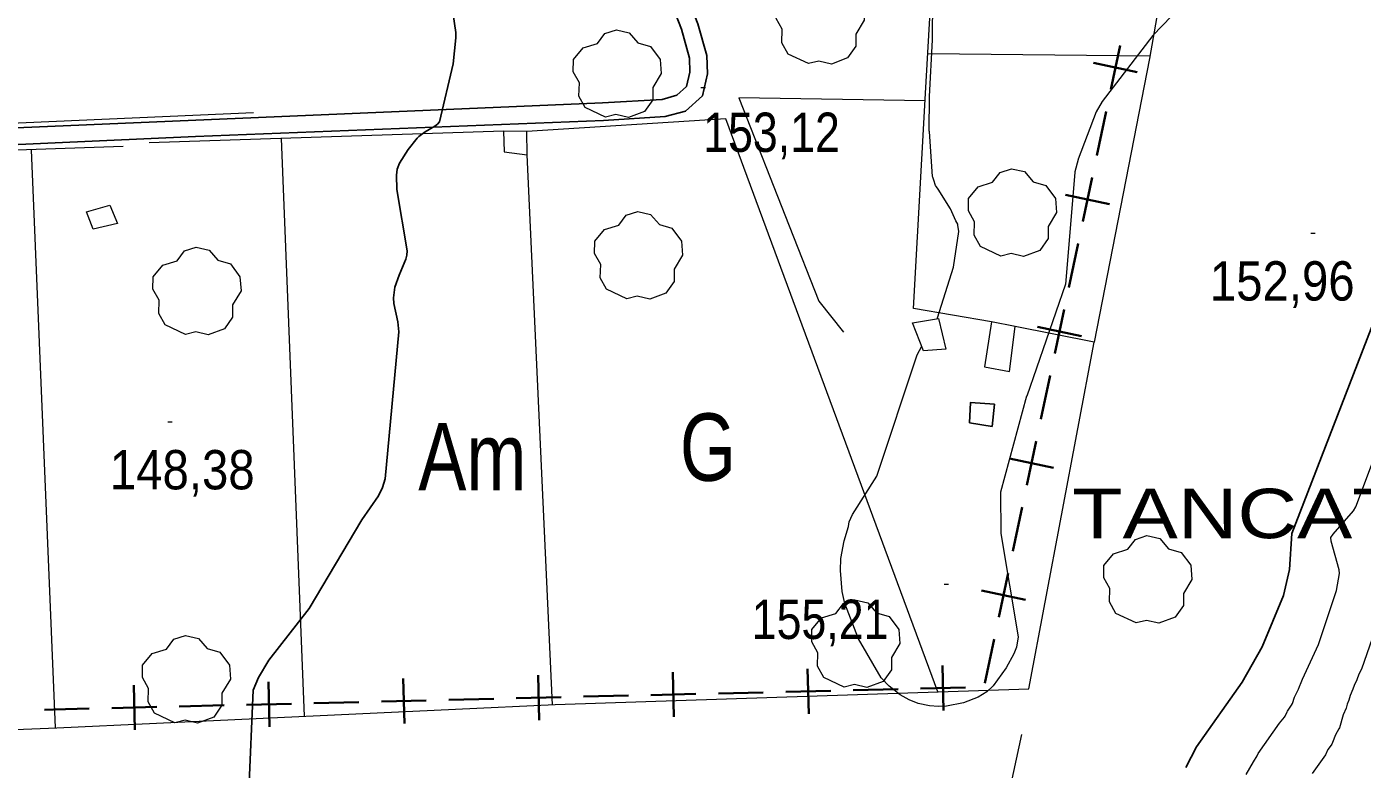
# Model space of a CAD drawing. Extents: x 480264 to 484872, y 4381275 to 4384491.
# Drawn here: x 480605 to 480902.2, y 4383797.7 to 4383962.9 of the extents above; entities that cross this region are included whole.
import ezdxf
from ezdxf.enums import TextEntityAlignment as Align

# ---------------------------------------------------------------- set-up
doc = ezdxf.new("R2010")
doc.units = 0
doc.header["$LTSCALE"] = 4
for name, color, linetype, lineweight in [('21', 7, 'Continuous', 25), ('29', 7, 'Continuous', 13), ('34', 7, 'Continuous', 35), ('38', 7, 'Continuous', 25), ('47', 7, 'Continuous', 13), ('51', 7, 'Continuous', 13), ('7', 7, 'Continuous', 13), ('8', 7, 'Continuous', 25), ('9', 7, 'Continuous', 13)]:
    doc.layers.add(name, color=color, linetype=linetype, lineweight=lineweight)
doc.layers.add('31', color=7, linetype='Continuous')
doc.layers.add('5', color=7, linetype='Continuous')

msp = doc.modelspace()

# ---------------------------------------------------------------- linework, layer by layer
at = {"layer": '21'}
msp.add_lwpolyline([(480814.77, 4383874.77), (480815.02, 4383879.32), (480820.31, 4383878.9), (480819.8, 4383873.96)], close=True, dxfattribs=at)
at = {"layer": '29'}
for points in [[(480778.98, 4383954.69), (480774.44, 4383956.81), (480773.03, 4383959.35), (480773.13, 4383962.33), (480771.76, 4383964.74), (480771.8, 4383967.49), (480773.96, 4383970.09), (480777.15, 4383971.09), (480778.8, 4383973.28), (480781.37, 4383974.11), (480784.23, 4383973.46), (480786.18, 4383971.19), (480788.99, 4383970.37), (480791.12, 4383967.52), (480791.36, 4383964.39), (480789.48, 4383961.24), (480789.48, 4383958.56), (480787.66, 4383955.95), (480784.04, 4383954.61), (480781.27, 4383955.24)], [(480733.82, 4383942.8), (480729.28, 4383944.92), (480727.87, 4383947.46), (480727.97, 4383950.44), (480726.6, 4383952.85), (480726.64, 4383955.6), (480728.8, 4383958.2), (480731.99, 4383959.2), (480733.64, 4383961.39), (480736.21, 4383962.22), (480739.07, 4383961.57), (480741.02, 4383959.3), (480743.83, 4383958.48), (480745.96, 4383955.63), (480746.2, 4383952.5), (480744.32, 4383949.35), (480744.32, 4383946.67), (480742.5, 4383944.06), (480738.88, 4383942.72), (480736.11, 4383943.35)], [(480821.76, 4383911.89), (480817.22, 4383914.01), (480815.81, 4383916.55), (480815.91, 4383919.53), (480814.54, 4383921.94), (480814.58, 4383924.69), (480816.74, 4383927.29), (480819.93, 4383928.29), (480821.58, 4383930.48), (480824.15, 4383931.31), (480827.01, 4383930.66), (480828.96, 4383928.39), (480831.77, 4383927.57), (480833.9, 4383924.72), (480834.14, 4383921.59), (480832.26, 4383918.44), (480832.26, 4383915.76), (480830.44, 4383913.15), (480826.82, 4383911.81), (480824.05, 4383912.44)], [(480738.57, 4383902.38), (480734.03, 4383904.5), (480732.62, 4383907.04), (480732.72, 4383910.02), (480731.35, 4383912.43), (480731.39, 4383915.18), (480733.55, 4383917.78), (480736.74, 4383918.78), (480738.39, 4383920.97), (480740.96, 4383921.8), (480743.82, 4383921.15), (480745.77, 4383918.88), (480748.58, 4383918.06), (480750.71, 4383915.21), (480750.95, 4383912.08), (480749.07, 4383908.93), (480749.07, 4383906.25), (480747.25, 4383903.64), (480743.63, 4383902.3), (480740.86, 4383902.93)], [(480640.33, 4383894.45), (480635.79, 4383896.57), (480634.38, 4383899.11), (480634.48, 4383902.09), (480633.11, 4383904.5), (480633.15, 4383907.25), (480635.31, 4383909.85), (480638.5, 4383910.85), (480640.15, 4383913.04), (480642.72, 4383913.87), (480645.58, 4383913.22), (480647.53, 4383910.95), (480650.34, 4383910.13), (480652.47, 4383907.28), (480652.71, 4383904.15), (480650.83, 4383901), (480650.83, 4383898.32), (480649.01, 4383895.71), (480645.39, 4383894.37), (480642.62, 4383895)], [(480851.87, 4383830.25), (480847.33, 4383832.37), (480845.92, 4383834.91), (480846.02, 4383837.89), (480844.65, 4383840.3), (480844.69, 4383843.05), (480846.85, 4383845.65), (480850.04, 4383846.65), (480851.69, 4383848.84), (480854.26, 4383849.67), (480857.12, 4383849.02), (480859.07, 4383846.75), (480861.88, 4383845.93), (480864.01, 4383843.08), (480864.25, 4383839.95), (480862.37, 4383836.8), (480862.37, 4383834.12), (480860.55, 4383831.51), (480856.93, 4383830.17), (480854.16, 4383830.8)], [(480786.9, 4383815.98), (480782.36, 4383818.1), (480780.95, 4383820.64), (480781.05, 4383823.62), (480779.68, 4383826.03), (480779.72, 4383828.78), (480781.88, 4383831.38), (480785.07, 4383832.38), (480786.72, 4383834.57), (480789.29, 4383835.4), (480792.15, 4383834.75), (480794.1, 4383832.48), (480796.91, 4383831.66), (480799.04, 4383828.81), (480799.28, 4383825.68), (480797.4, 4383822.53), (480797.4, 4383819.85), (480795.58, 4383817.24), (480791.96, 4383815.9), (480789.19, 4383816.53)], [(480637.96, 4383808.05), (480633.42, 4383810.17), (480632.01, 4383812.71), (480632.11, 4383815.69), (480630.74, 4383818.1), (480630.78, 4383820.85), (480632.94, 4383823.45), (480636.13, 4383824.45), (480637.78, 4383826.64), (480640.35, 4383827.47), (480643.21, 4383826.82), (480645.16, 4383824.55), (480647.97, 4383823.73), (480650.1, 4383820.88), (480650.34, 4383817.75), (480648.46, 4383814.6), (480648.46, 4383811.92), (480646.64, 4383809.31), (480643.02, 4383807.97), (480640.25, 4383808.6)]]:
    msp.add_lwpolyline(points, close=True, dxfattribs=at)
at = {"layer": '34'}
for p, q in [((480848.27, 4383958.71), (480846.2, 4383948.92)), ((480842.34, 4383954.85), (480852.12, 4383952.78)), ((480845.16, 4383944.03), (480843.08, 4383934.25)), ((480842.05, 4383929.36), (480839.97, 4383919.58)), ((480836.12, 4383925.51), (480845.9, 4383923.43)), ((480838.93, 4383914.69), (480836.86, 4383904.9)), ((480835.82, 4383900.01), (480833.75, 4383890.23)), ((480829.89, 4383896.16), (480839.67, 4383894.08)), ((480832.71, 4383885.34), (480830.63, 4383875.56)), ((480829.6, 4383870.66), (480827.52, 4383860.88)), ((480823.67, 4383866.81), (480833.45, 4383864.74)), ((480826.48, 4383855.99), (480824.41, 4383846.21)), ((480823.37, 4383841.32), (480821.3, 4383831.54)), ((480817.44, 4383837.46), (480827.22, 4383835.39)), ((480820.26, 4383826.64), (480818.18, 4383816.86)), ((480748.78, 4383819.33), (480749.02, 4383809.33)), ((480778.77, 4383820.05), (480779.01, 4383810.06)), ((480808.76, 4383820.78), (480809, 4383810.78)), ((480628.82, 4383816.43), (480629.06, 4383806.43)), ((480658.81, 4383817.16), (480659.05, 4383807.16)), ((480688.8, 4383817.88), (480689.04, 4383807.88)), ((480718.79, 4383818.61), (480719.03, 4383808.61)), ((480708.91, 4383813.37), (480698.92, 4383813.12)), ((480723.91, 4383813.73), (480713.91, 4383813.49)), ((480738.9, 4383814.09), (480728.91, 4383813.85)), ((480753.9, 4383814.45), (480743.9, 4383814.21)), ((480768.9, 4383814.81), (480758.9, 4383814.57)), ((480783.89, 4383815.18), (480773.89, 4383814.93)), ((480798.89, 4383815.54), (480788.89, 4383815.3)), ((480813.88, 4383815.9), (480803.89, 4383815.66)), ((480633.93, 4383811.55), (480623.94, 4383811.31)), ((480648.93, 4383811.92), (480638.93, 4383811.67)), ((480663.93, 4383812.28), (480653.93, 4383812.04)), ((480678.92, 4383812.64), (480668.92, 4383812.4)), ((480693.92, 4383813), (480683.92, 4383812.76))]:
    msp.add_line(p, q, dxfattribs=at)
msp.add_lwpolyline([(480618.94, 4383811.19), (480611, 4383811), (480608.95, 4383810.88)], dxfattribs=at)
at = {"layer": '38'}
for points in [[(480522.56, 4383936.97), (480733.12, 4383945.95), (480746.43, 4383946.75), (480749.64, 4383947.65), (480751.85, 4383949.62), (480752.57, 4383952.77), (480752.47, 4383955.89), (480750.69, 4383962.33), (480714.17, 4384055.97), (480680.61, 4384144.02)], [(480522.55, 4383933.08), (480642.54, 4383938.48), (480733.32, 4383942.07), (480747.08, 4383942.91), (480751.56, 4383944.15), (480755.36, 4383947.56), (480756.46, 4383952.39), (480756.33, 4383956.48), (480754.37, 4383963.56), (480717.79, 4384057.37), (480693.05, 4384122.28)]]:
    msp.add_lwpolyline(points, dxfattribs=at)
at = {"layer": '47'}
for points in [[(480716.33, 4383934.41), (480716.26, 4383939.61), (480711.11, 4383939.66), (480711.23, 4383935.08)], [(480619.81, 4383917.85), (480618.29, 4383921.72), (480623.49, 4383923.23), (480625.23, 4383919.15)], [(480809.5, 4383891.2), (480804.57, 4383890.79), (480802.11, 4383897.06), (480807.9, 4383898.01)], [(480818.11, 4383887.23), (480823.67, 4383886.21), (480824.91, 4383896.24), (480819.7, 4383897.23)]]:
    msp.add_lwpolyline(points, close=True, dxfattribs=at)
at = {"layer": '51'}
for p, q in [((480854.89, 4383956.33), (480805.49, 4383956.91)), ((480711.11, 4383939.66), (480632.28, 4383937.08)), ((480661.62, 4383938.05), (480666.74, 4383809.49)), ((480626.49, 4383936.29), (480551.12, 4383933.51)), ((480611.44, 4383806.93), (480606.08, 4383935.55)), ((480721.99, 4383812.04), (480716.33, 4383934.41))]:
    msp.add_line(p, q, dxfattribs=at)
for points in [[(480819.7, 4383897.23), (480802.34, 4383900.24), (480805.05, 4383949.41), (480808.72, 4384012.66), (480817.16, 4384093.4), (480822.07, 4384143.68)], [(480890.88, 4384143.52), (480884.7, 4384114.51), (480878.44, 4384084.04), (480867.35, 4384027.57), (480854.79, 4383955.8), (480842.5, 4383892.71)], [(480804.89, 4383946.45), (480763.47, 4383947.06), (480774.66, 4383918.6), (480781.23, 4383901.85), (480786.77, 4383894.92)], [(480655.5, 4383943.75), (480545.81, 4383938.9), (480522.56, 4383938)], [(480807.71, 4383814.91), (480760.54, 4383942.38), (480716.26, 4383939.61)], [(480555.97, 4383804.66), (480611.7, 4383806.94), (480722.6, 4383812.07), (480828.01, 4383815.59), (480842.5, 4383892.71), (480824.91, 4383896.24)], [(480826.37, 4383805.45), (480807.93, 4383720.33), (480792.92, 4383654.78), (480811.87, 4383621.48), (480827.76, 4383606.43)]]:
    msp.add_lwpolyline(points, dxfattribs=at)
at = {"layer": '7'}
for p, q in [((480755.02, 4383949.42), (480756.02, 4383949.42)), ((480890.69, 4383916.99), (480891.69, 4383916.99)), ((480636.4, 4383874.98), (480637.4, 4383874.98)), ((480809.14, 4383838.88), (480810.14, 4383838.88))]:
    msp.add_line(p, q, dxfattribs=at)
at = {"layer": '8'}
for points in [[(480862.89, 4383798.1), (480865.25, 4383802.7), (480875.42, 4383817.04), (480879.88, 4383824.95), (480884.63, 4383836.33), (480885.94, 4383842.16), (480886.46, 4383850.16), (480917.9, 4383931.19), (480923, 4383943.93), (480924.33, 4383950.54), (480925.23, 4383964), (480925.86, 4383987.58), (480923.34, 4384059.71), (480904.52, 4384133.89), (480904.41, 4384138.63), (480905.53, 4384143.48)], [(480698.69, 4383973.73), (480700.5, 4383961.63), (480700.51, 4383960.42), (480699.9, 4383954.67), (480696.85, 4383941.73), (480696.38, 4383941.2), (480695.85, 4383940.77), (480693.64, 4383939.52), (480692.27, 4383938.5), (480691.87, 4383938.1), (480689.86, 4383935.61), (480687.95, 4383932.54), (480687.44, 4383931.24), (480687.29, 4383929.91), (480687.39, 4383926.67), (480689.65, 4383913.02), (480689.59, 4383912.09), (480689.39, 4383911.19), (480687.88, 4383907.64), (480686.94, 4383904.95), (480686.61, 4383902.58), (480686.66, 4383901.31), (480687.59, 4383897.22), (480687.78, 4383895.03), (480684.76, 4383862.28), (480684.16, 4383860.38), (480683.29, 4383858.52), (480679.57, 4383853.19), (480667.85, 4383833.43), (480658.86, 4383821.99), (480656.55, 4383818.12), (480655.4, 4383815.31), (480654.42, 4383792.89)]]:
    msp.add_lwpolyline(points, dxfattribs=at)
at = {"layer": '9'}
for points in [[(480807.57, 4383897.96), (480807.69, 4383898.17), (480811.22, 4383909.4), (480812.41, 4383917.36), (480812.21, 4383918.74), (480812.16, 4383918.94), (480811.76, 4383919.71), (480810.53, 4383922.42), (480807.84, 4383926.76), (480807.42, 4383927.31), (480807.25, 4383927.6), (480806.81, 4383928.73), (480806.6, 4383929.46), (480806.58, 4383929.61), (480805.86, 4383939.6), (480805.85, 4383939.65), (480805.84, 4383939.68), (480805.87, 4383947.28), (480805.86, 4383947.35), (480806.55, 4383959.99), (480806.54, 4383960.02), (480806.54, 4383960.04), (480806.69, 4383978.14)], [(480859.73, 4383965.26), (480855.54, 4383960.99), (480844.33, 4383946.27), (480842.93, 4383943.94), (480838.96, 4383933.41), (480838.92, 4383933.34), (480838.23, 4383930.64), (480838.2, 4383930.56), (480838.2, 4383930.53), (480838.2, 4383930.5), (480836.14, 4383905.65), (480827.51, 4383880.74), (480827.48, 4383880.67), (480821.71, 4383859.32), (480821.72, 4383850.16), (480825.62, 4383827.17), (480825.21, 4383824.89), (480824.63, 4383823.39), (480822.93, 4383820.28), (480820.06, 4383816.24), (480818.67, 4383814.91), (480816.68, 4383813.74), (480813.42, 4383812.51), (480809.65, 4383811.76), (480807.91, 4383811.65), (480805.89, 4383811.77), (480803.35, 4383812.35), (480801.34, 4383813.13), (480799.34, 4383814.23), (480796.88, 4383816.17), (480795.14, 4383818.03), (480790.07, 4383826.73), (480787.06, 4383834.6), (480786.47, 4383837.25), (480786.06, 4383841.89), (480786.14, 4383844.59), (480786.86, 4383848.51), (480787.84, 4383851.7), (480788.02, 4383852.76), (480788.73, 4383854.41), (480794.15, 4383862.94), (480803.17, 4383889.92), (480804.15, 4383891.86)], [(480876.35, 4383796.54), (480877.93, 4383799.32), (480878.77, 4383800.66), (480879.04, 4383801.21), (480883.77, 4383807.95), (480884.85, 4383809.25), (480885.03, 4383809.53), (480885.44, 4383810.45), (480885.52, 4383810.6), (480886.45, 4383811.95), (480886.62, 4383812.29), (480887.09, 4383813.71), (480888, 4383815.5), (480888.2, 4383816.1), (480888.59, 4383816.99), (480888.85, 4383817.75), (480892.45, 4383825.46), (480896.41, 4383837.48), (480897.07, 4383841.23), (480897, 4383842.04), (480895.26, 4383848.45), (480895.2, 4383849.28), (480895.71, 4383850), (480900.23, 4383855.18), (480900.74, 4383856.07), (480916.61, 4383898.35)], [(480907.32, 4383835.32), (480901.96, 4383819.98), (480901.43, 4383818.86), (480900.99, 4383817.6), (480900.36, 4383816.3), (480900.07, 4383815.5), (480899.46, 4383814.13), (480899.15, 4383813.04), (480898.82, 4383812.17), (480898.57, 4383811.26), (480897.89, 4383809.77), (480897.07, 4383806.91), (480896.98, 4383806.69), (480896.19, 4383805.36), (480895.56, 4383803.62), (480895.37, 4383803.27), (480894.57, 4383802.18), (480894.5, 4383802.06), (480893.97, 4383800.93), (480891.04, 4383796.78)]]:
    msp.add_lwpolyline(points, dxfattribs=at)

# ---------------------------------------------------------------- texts
at = {"layer": '31', "width": 0.8}
for s, p in [('G', (480756.58, 4383861.87)), ('Am', (480704.175, 4383859.77))]:
    msp.add_text(s, height=15, dxfattribs=at).set_placement(p, align=Align.CENTER)
at = {"layer": '5', "width": 1.25}
msp.add_text('TANCAT DES VOLTOR', height=11, dxfattribs=at).set_placement((480837.62, 4383849.11))
at = {"layer": '7'}
for s, width, p in [('153,12', 0.85, (480755.52, 4383935.05)), ('152,96', 0.9, (480868.26, 4383901.98)), ('148,38', 0.9, (480623.52, 4383859.97)), ('155,21', 0.85, (480766.33, 4383826.68))]:
    msp.add_text(s, height=8.75, dxfattribs=dict(at, width=width)).set_placement(p)

doc.saveas('drawing.dxf')
